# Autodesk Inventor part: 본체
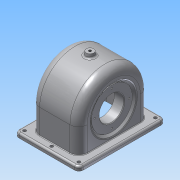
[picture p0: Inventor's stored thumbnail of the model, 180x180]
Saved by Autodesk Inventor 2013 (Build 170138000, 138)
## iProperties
Created: 2015-09
Part Number: 본체
Material: 알루미늄 6061
Document SubType Name: Modeling
Designer: Administrator
Density: 1 g/cm^3
Author: Administrator
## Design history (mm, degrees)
sketch "스케치1"
  geometry: L1 (-57, 0)-(57, 0); L2 (0, 0)-(0, 47); L3 (-57, 0)-(-57, 47); L4 (57, 0)-(57, 47); A1 r 57 centre (0, 47) between (57, 47) and (-57, 47); 1 further point
  constraints: 8 end point, 2 coincident, 2 point on circle, 1 centre point, 1 horizontal, 1 midpoint, 1 parallel, 1 perpendicular
  dimensions: "d0" = 114 distance of L1.start L1.end; "d1" = 47 distance of L2.start L2.end; "d2" = 57 radius of A1
extrude "돌출1" new body sketch "스케치1" stored distance "d3" = 77; taper "d4" = 0 deg
feature "쉘1" dims "d5" = 5
sketch "스케치2"
  geometry: L1 (47, -57)-(0, -57) reference; L2 (0, -57)-(0, 57) reference; L3 (0, 57)-(47, 57) reference; C1 r 31 at (47, 0); A1 r 57 centre (47, 0) between (47, -57) and (47, 57) reference; 1 further point
  constraints: 1 centre point, 1 coincident
  dimensions: "d6" = 62 diameter of C1
extrude "돌출2" join sketch "스케치2" distance "d7" = 10; taper "d8" = 0 deg
sketch "스케치3"
  geometry: C1 r 31 at (0, 0) reference; C2 r 20 at (0, 0); 1 further point
  constraints: 1 centre point, 1 coincident
  dimensions: "d9" = 40 diameter of C2
extrude "돌출3" cut sketch "스케치3" stored distance "d10" = 10; taper "d11" = 0 deg
fillet "모깎기1" dims "d12" = 14
fillet "모깎기2" dims "d13" = 3
chamfer "모따기1" distance "d14" = 1; stored, may be unused: second distance "d15" = 2, angle "d16" = 45 deg
fillet "모깎기3" dims "d17" = 9
sketch "스케치4"
  geometry: C1 r 21 at (0, 0) reference; C2 r 31 at (0, 0) reference; A1 r 24 centre (0, 0) between (0, 24) and (-24, 0); 3 further points
  constraints: 4 point on circle, 1 centre point, 1 coincident
  dimensions: "d18" = 48 diameter of A1
hole "구멍1" sketch "스케치4" at (0, 24), (-24, 0), (0, -24), (24, 0) diameter "d19" = 2.459; stored, may be unused: countersink angle "d23" = 90 deg, drill point angle "d25" = 118 deg; dims "d20" = 6, "d21" = 4, "d22" = 2, "d24" = 8
sketch "스케치5"
  geometry: L1 (0, 43)-(-47, 43) reference; L2 (-47, -43)-(0, -43) reference; L3 (0, 43)-(0, -43) reference; C1 r 28 at (-47, 0); A1 r 43 centre (-47, 0) between (-47, 43) and (-47, -43) reference; 1 further point
  constraints: 1 centre point, 1 coincident
  dimensions: "d26" = 56 diameter of C1
extrude "돌출4" join sketch "스케치5" distance "d27" = 19; taper "d28" = 0 deg
sketch "스케치6"
  geometry: L1 (0, 43)-(-47, 43) reference; L2 (-47, -43)-(0, -43) reference; L3 (0, 43)-(0, -43) reference; C1 r 33 at (-47, 0); A1 r 43 centre (-47, 0) between (-47, 43) and (-47, -43) reference; 1 further point
  constraints: 1 centre point, 1 coincident
  dimensions: "d29" = 66 diameter of C1
extrude "돌출5" cut sketch "스케치6" distance "d30" = 3; taper "d31" = 0 deg
sketch "스케치7"
  geometry: L1 (0, 51.66)-(47, 51.66) reference; L2 (47, 51.66)-(47, -51.66) reference; L3 (47, -51.66)-(0, -51.66) reference; C1 r 33 at (0, 0) reference; C2 r 20 at (0, 0); A1 r 51.66 centre (0, 0) between (0, 51.66) and (0, -51.66) reference; 1 further point
  constraints: 1 centre point, 1 coincident
  dimensions: "d32" = 40 diameter of C2
extrude "돌출6" cut sketch "스케치7" stored distance "d33" = 3; taper "d34" = 0 deg
feature "면 기울기1" dims angle "d35" = 40 deg
node "작업 평면1"
sketch "스케치8"
  geometry: L1 (44, -19)-(58, -7.253) reference; L2 (58, -7.253)-(58, 0) reference; L3 (58, 0)-(63, 0) reference; L4 (63, 0)-(63, -14) reference; L5 (63, -14)-(60, -14) reference; L6 (60, -14)-(60, -27) reference; L7 (60, -27)-(44, -27) reference; L8 (44, -27)-(44, -19) reference; L9 (-14, -13)-(-14, 0) reference; L10 (-14, 0)-(-9, 0) reference; L11 (-9, 0)-(-9, -27) reference; L12 (-9, -27)-(-23, -27) reference; L13 (-23, -27)-(-24, -26) reference; L14 (-24, -26)-(-24, -24.229) reference; L15 (-24, -24.229)-(-16, -24.229) reference; L16 (-16, -24.229)-(-15.261, -23) reference; L17 (-15.261, -23)-(-16, -21.77) reference; L18 (-16, -21.77)-(-24, -21.77) reference; L19 (-24, -21.77)-(-24, -16) reference; L20 (-24, -16)-(-17, -16) reference; L21 (49, -104)-(0, -104) reference; L22 (-14, -90)-(-14, -81) reference; L23 (-17, -78)-(-24, -78) reference; L24 (-24, -78)-(-24, -72.23) reference; L25 (-24, -72.23)-(-16, -72.23) reference; L26 (-16, -72.23)-(-15.261, -71) reference; L27 (-15.261, -71)-(-16, -69.77) reference; L28 (-16, -69.77)-(-24, -69.77) reference; L29 (-24, -69.77)-(-24, -68) reference; L30 (-24, -68)-(-23, -67) reference; L31 (-23, -67)-(-9, -67) reference; L32 (-9, -67)-(-9, -90) reference; L33 (0, -99)-(49, -99) reference; L34 (58, -90)-(58, -86.747) reference; L35 (58, -86.747)-(44, -75) reference; L36 (44, -75)-(44, -67) reference; L37 (44, -67)-(60, -67) reference; L38 (60, -67)-(60, -80) reference; L39 (60, -80)-(63, -80) reference; L40 (63, -80)-(63, -90) reference; L41 (58, -86.747)-(44, -75); L42 (63, -84.416)-(58.79, -80.883); L43 (63, -84.416)-(63, -80); L44 (63, -80)-(59.111, -80); L45 (60, -67)-(60, -27); L46 (60, -47)-(88.26, -47); A1 r 3 centre (-17, -13) between (-17, -16) and (-14, -13) reference; A2 r 14 centre (49, -90) between (49, -104) and (63, -90) reference; A3 r 14 centre (0, -90) between (-14, -90) and (0, -104) reference; A4 r 3 centre (-17, -81) between (-14, -81) and (-17, -78) reference; A5 r 9 centre (0, -90) between (-9, -90) and (0, -99) reference; A6 r 9 centre (49, -90) between (49, -99) and (58, -90) reference; A7 r 0.5 centre (59.111, -80.5) between (59.111, -80) and (58.79, -80.883); 1 further point
  constraints: 12 end point, 3 perpendicular, 2 collinear, 2 point on circle, 2 tangent, 1 centre point, 1 midpoint, 1 parallel, 1 point on line
  dimensions: "d36" = 5 distance between parallel lines of L35 L42; "d37" = 0.5 radius of A7
revolve "회전1" sketch "스케치8" stored, may be unused: angle "d38" = 90 deg
sketch "스케치9"
  geometry: L1 (0, 51.66)-(47, 51.66) reference; L2 (47, 51.66)-(47, -51.66) reference; L3 (47, -51.66)-(0, -51.66) reference; C1 r 34.899 at (0, 0) reference; C2 r 33 at (0, 0) reference; C3 r 20 at (0, 0) reference; A1 r 51.66 centre (0, 0) between (0, 51.66) and (0, -51.66) reference; A2 r 28 centre (0, 0) between (-28, 0) and (0, -28); 3 further points
  constraints: 4 point on circle, 1 centre point, 1 coincident
  dimensions: "d42" = 56 diameter of A2
hole "구멍2" sketch "스케치9" at (-28, 0), (0, -28), (28, 0), (0, 28) diameter "d43" = 2.459; stored, may be unused: countersink angle "d47" = 82 deg, drill point angle "d49" = 118 deg; dims "d44" = 7, "d45" = 3.023, "d46" = 2, "d48" = 9
sketch "스케치10"
  geometry: L1 (-33.5, 43)-(-33.5, -43) reference; L2 (-24.5, -52)-(24.5, -52) reference; L3 (33.5, -43)-(33.5, 43) reference; L4 (24.5, 52)-(-24.5, 52) reference; L5 (-38.5, -43)-(-38.5, 43) reference; L6 (-24.5, 57)-(24.5, 57) reference; L7 (38.5, 43)-(38.5, -43) reference; L8 (24.5, -57)-(-24.5, -57) reference; L9 (-45, 70)-(45, 70); L10 (52, 63)-(52, -63); L11 (45, -70)-(-45, -70); L12 (-52, -63)-(-52, 63); L13 (0, 70)-(0, 62); L14 (-38.5, 0)-(38.5, 0); C1 r 2.5 at (-44, 62); C2 r 2.5 at (0, 62); C3 r 2.5 at (44, 62); C4 r 2.5 at (-44, -62); C5 r 2.5 at (0, -62); C6 r 2.5 at (44, -62); A1 r 9 centre (-24.5, 43) between (-24.5, 52) and (-33.5, 43) reference; A2 r 9 centre (-24.5, -43) between (-33.5, -43) and (-24.5, -52) reference; A3 r 9 centre (24.5, -43) between (24.5, -52) and (33.5, -43) reference; A4 r 9 centre (24.5, 43) between (33.5, 43) and (24.5, 52) reference; A5 r 14 centre (-24.5, 43) between (-24.5, 57) and (-38.5, 43) reference; A6 r 14 centre (24.5, 43) between (38.5, 43) and (24.5, 57) reference; A7 r 14 centre (24.5, -43) between (24.5, -57) and (38.5, -43) reference; A8 r 14 centre (-24.5, -43) between (-38.5, -43) and (-24.5, -57) reference; A9 r 7 centre (-45, 63) between (-45, 70) and (-52, 63); A10 r 7 centre (45, 63) between (52, 63) and (45, 70); A11 r 7 centre (45, -63) between (45, -70) and (52, -63); A12 r 7 centre (-45, -63) between (-52, -63) and (-45, -70); 5 further points
  constraints: 12 end point, 10 centre point, 8 point on circle, 8 tangent, 6 point on line, 4 midpoint, 3 equal radius, 3 symmetric about line, 2 parallel, 1 coincident, 1 horizontal, 1 horizontal alignment, 1 perpendicular, 1 vertical alignment, 3 other
  dimensions: "d50" = 104 distance of point (52, -70) point (-52, -70); "d51" = 140 distance of point (52, 70) point (52, -70); "d52" = 7 radius of A9; "d57" = 5 diameter of C1; "d58" = 5 diameter of C2; "d59" = 5 diameter of C3
extrude "돌출7" join sketch "스케치10" distance "d60" = 7; taper "d61" = 0 deg
fillet "모깎기4" dims "d62" = 3
node "작업 평면3"
  node "작업 평면2"
sketch "스케치11"
  geometry: C1 r 6 at (0, 0); 1 further point
  constraints: 1 centre point, 1 coincident
  dimensions: "d64" = 12 diameter of C1
extrude "돌출8" join sketch "스케치11" stored distance "d65" = 7; taper "d66" = 0 deg
feature "면 기울기2" dims angle "d67" = 10 deg
fillet "모깎기5" dims "d68" = 3
sketch "스케치12"
  geometry: C1 r 6 at (0, 0) reference; 1 further point
hole "구멍3" sketch "스케치12" at (0, 0) diameter "d69" = 4.134; stored, may be unused: countersink angle "d73" = 82 deg, drill point angle "d75" = 118 deg; dims "d70" = 10, "d71" = 3.023, "d72" = 2, "d74" = 20
sketch "스케치13"
  geometry: L1 (73.5, 40)-(49, 40) reference; L2 (49, 40)-(0, 40) reference; L3 (0, 40)-(-24.5, 40) reference; L4 (-27.5, 43)-(-27.5, 47) reference; L5 (-27.5, 47)-(76.5, 47) reference; L6 (76.5, 47)-(76.5, 43) reference; L7 (49, 40)-(49, 0) reference; L8 (0, 0)-(49, 0) reference; L9 (0, 0)-(0, 40) reference; L10 (63, 0)-(63, 40) reference; A1 r 3 centre (73.5, 43) between (73.5, 40) and (76.5, 43) reference; A2 r 3 centre (-24.5, 43) between (-27.5, 43) and (-24.5, 40) reference; 2 further points
  constraints: 1 other
  dimensions: "d76" = 30 vertical distance of point (24.5, 17) L5.end; "d77" = 38.5 horizontal distance of point (24.5, 17) L10.end
feature "엠보싱1" sketch "스케치13" dims "d78" = 0.5, "d79" = 0
fillet "모깎기6" dims "d80" = 1
chamfer "모따기3" distance "d81" = 1; stored, may be unused: second distance "d82" = 2, angle "d83" = 45 deg
node "솔리드1"
node "절단 모서리 투영1"
node "절단 모서리 투영2"
node "절단 모서리 투영3"
node "절단 모서리 투영4"
node "절단 모서리 투영5"
node "절단 모서리 투영6"
node "절단 모서리 투영7"
node "절단 모서리 투영8"
node "절단 모서리 투영9"
node "절단 모서리 투영10"
node "절단 모서리 투영11"
other parameters: "d63" = 6
